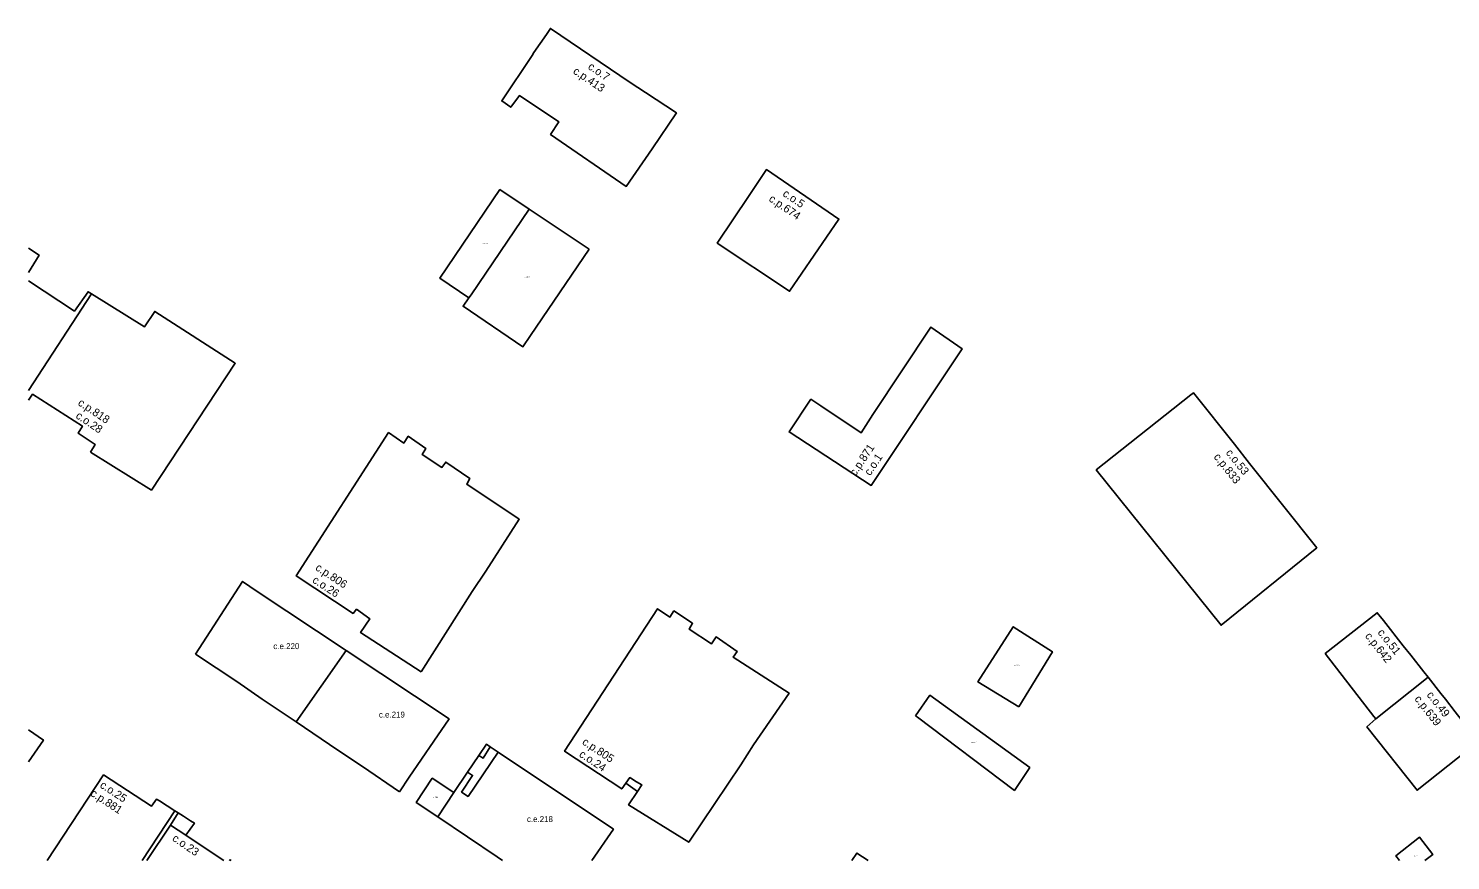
# Model space of a CAD drawing. Extents: x -600391 to -599491, y -1160176 to -1159402.
# Drawn here: x -600391 to -600213.3, y -1160176.1 to -1160072.1 of the extents above; entities that cross this region are included whole.
import ezdxf

# ---------------------------------------------------------------- set-up
doc = ezdxf.new("R2010")
doc.units = 0
for name, color, linetype in [('Level 10', 7, 'Continuous'), ('Level 12', 7, 'Continuous'), ('Level 23', 7, 'Continuous'), ('Level 24', 7, 'Continuous'), ('Level 25', 7, 'Continuous'), ('Level 61', 7, 'Continuous'), ('Level 62', 7, 'Continuous')]:
    doc.layers.add(name, color=color, linetype=linetype)

msp = doc.modelspace()

# ---------------------------------------------------------------- linework, layer by layer
at = {"layer": 'Level 61'}
for p, q in [((-600391.01, -1160099.58), (-600389.68, -1160100.46)), ((-600389.68, -1160100.46), (-600391.01, -1160102.63)), ((-600391.01, -1160103.69), (-600385.27, -1160107.44)), ((-600391.01, -1160117.37), (-600383.14, -1160105.31)), ((-600383.14, -1160105.31), (-600391.01, -1160117.37)), ((-600390.49, -1160117.84), (-600391.01, -1160118.58)), ((-600391.01, -1160159.77), (-600389.13, -1160161.03)), ((-600389.13, -1160161.03), (-600391.01, -1160163.76)), ((-600388.66, -1160176.08), (-600381.61, -1160165.38)), ((-600372.71, -1160169.85), (-600376.79, -1160176.08)), ((-600376.79, -1160176.08), (-600372.71, -1160169.85)), ((-600376.2, -1160176.08), (-600373.25, -1160171.64)), ((-600373.25, -1160171.64), (-600376.2, -1160176.08)), ((-600317.91, -1160172.18), (-600320.58, -1160176.08)), ((-600371.18, -1160173.02), (-600366.61, -1160176.08)), ((-600365.92, -1160176.08), (-600365.83, -1160175.97)), ((-600365.83, -1160175.97), (-600365.67, -1160176.08)), ((-600331.75, -1160176.08), (-600332.43, -1160175.62)), ((-600288.1, -1160176.08), (-600287.48, -1160175.15)), ((-600287.48, -1160175.15), (-600286.05, -1160176.08)), ((-600219.66, -1160176.08), (-600220.12, -1160175.48)), ((-600215.49, -1160175.31), (-600216.48, -1160176.08))]:
    msp.add_line(p, q, dxfattribs=at)
for points in [[(-600327.83, -1160075.17), (-600326.26, -1160072.9)], [(-600326.26, -1160072.9), (-600325.77, -1160072.15)], [(-600325.77, -1160072.15), (-600315.8, -1160078.89)], [(-600331.86, -1160081.2), (-600328.06, -1160075.52)], [(-600328.06, -1160075.52), (-600327.83, -1160075.17)], [(-600315.8, -1160078.89), (-600313.88, -1160080.16)], [(-600330.74, -1160082), (-600331.86, -1160081.2)], [(-600329.65, -1160080.53), (-600330.74, -1160082)], [(-600324.72, -1160083.83), (-600329.65, -1160080.53)], [(-600313.88, -1160080.16), (-600310.04, -1160082.7)], [(-600310.04, -1160082.7), (-600313.05, -1160087.19)], [(-600325.76, -1160085.39), (-600324.72, -1160083.83)], [(-600316.29, -1160091.88), (-600325.76, -1160085.39)], [(-600313.05, -1160087.19), (-600316.29, -1160091.88)], [(-600300.94, -1160093), (-600298.78, -1160089.78)], [(-600298.78, -1160089.78), (-600289.73, -1160095.96)], [(-600339.59, -1160103.35), (-600332.09, -1160092.28)], [(-600332.09, -1160092.28), (-600328.45, -1160094.71)], [(-600304.92, -1160098.95), (-600300.94, -1160093)], [(-600335.7, -1160105.41), (-600328.45, -1160094.71)], [(-600328.45, -1160094.71), (-600335.7, -1160105.41)], [(-600328.45, -1160094.71), (-600320.95, -1160099.71)], [(-600289.73, -1160095.96), (-600295.89, -1160104.97)], [(-600295.89, -1160104.97), (-600304.92, -1160098.95)], [(-600320.95, -1160099.71), (-600328.26, -1160110.5)], [(-600335.97, -1160105.81), (-600339.59, -1160103.35)], [(-600385.27, -1160107.44), (-600383.56, -1160105.03)], [(-600383.56, -1160105.03), (-600383.14, -1160105.31)], [(-600383.14, -1160105.31), (-600376.51, -1160109.43)], [(-600336.68, -1160106.85), (-600335.97, -1160105.81)], [(-600335.97, -1160105.81), (-600335.7, -1160105.41)], [(-600335.7, -1160105.41), (-600335.97, -1160105.81)], [(-600376.51, -1160109.43), (-600375.23, -1160107.5)], [(-600375.23, -1160107.5), (-600365.17, -1160113.96)], [(-600329.21, -1160111.91), (-600336.68, -1160106.85)], [(-600285.49, -1160120.38), (-600278.22, -1160109.45)], [(-600278.22, -1160109.45), (-600274.33, -1160112.15)], [(-600328.26, -1160110.5), (-600329.21, -1160111.91)], [(-600274.33, -1160112.15), (-600285.69, -1160129.22)], [(-600365.17, -1160113.96), (-600375.65, -1160129.81)], [(-600384.27, -1160121.81), (-600390.49, -1160117.84)], [(-600295.94, -1160122.55), (-600293.23, -1160118.46)], [(-600293.23, -1160118.46), (-600291.98, -1160119.29)], [(-600257.57, -1160127.29), (-600245.75, -1160117.93)], [(-600245.75, -1160117.93), (-600245.57, -1160117.78)], [(-600245.57, -1160117.78), (-600245.41, -1160117.66)], [(-600245.41, -1160117.66), (-600240.3, -1160124.09)], [(-600291.98, -1160119.29), (-600286.95, -1160122.66)], [(-600286.95, -1160122.66), (-600285.49, -1160120.38)], [(-600384.8, -1160122.69), (-600384.27, -1160121.81)], [(-600382.65, -1160124.12), (-600384.8, -1160122.69)], [(-600357.55, -1160140.52), (-600346.01, -1160122.62)], [(-600346.01, -1160122.62), (-600344.11, -1160123.93)], [(-600285.69, -1160129.22), (-600295.94, -1160122.55)], [(-600383.27, -1160125.06), (-600382.65, -1160124.12)], [(-600344.11, -1160123.93), (-600343.55, -1160123.08)], [(-600343.55, -1160123.08), (-600341.34, -1160124.63)], [(-600240.3, -1160124.09), (-600238.4, -1160126.47)], [(-600375.65, -1160129.81), (-600383.27, -1160125.06)], [(-600341.34, -1160124.63), (-600341.82, -1160125.36)], [(-600341.82, -1160125.36), (-600339.33, -1160126.98)], [(-600339.33, -1160126.98), (-600338.85, -1160126.31)], [(-600338.85, -1160126.31), (-600335.86, -1160128.36)], [(-600241.96, -1160146.7), (-600257.57, -1160127.29)], [(-600238.4, -1160126.47), (-600230.01, -1160137.02)], [(-600335.86, -1160128.36), (-600336.24, -1160129.07)], [(-600336.24, -1160129.07), (-600329.67, -1160133.45)], [(-600329.67, -1160133.45), (-600333.84, -1160139.93)], [(-600230.01, -1160137.02), (-600241.96, -1160146.7)], [(-600333.84, -1160139.93), (-600335.54, -1160142.49)], [(-600370.15, -1160150.29), (-600364.25, -1160141.21)], [(-600364.25, -1160141.21), (-600362.41, -1160142.46)], [(-600350.43, -1160145.22), (-600357.55, -1160140.52)], [(-600362.41, -1160142.46), (-600351.29, -1160149.85)], [(-600335.54, -1160142.49), (-600341.92, -1160152.51)], [(-600350, -1160144.7), (-600350.43, -1160145.22)], [(-600348.35, -1160145.88), (-600350, -1160144.7)], [(-600324, -1160162.42), (-600312.38, -1160144.63)], [(-600312.38, -1160144.63), (-600310.85, -1160145.67)], [(-600310.85, -1160145.67), (-600310.34, -1160144.89)], [(-600310.34, -1160144.89), (-600308, -1160146.44)], [(-600228.95, -1160150.22), (-600222.45, -1160145.12)], [(-600222.45, -1160145.12), (-600221.68, -1160146.1)], [(-600349.5, -1160147.61), (-600348.35, -1160145.88)], [(-600308, -1160146.44), (-600308.43, -1160147.18)], [(-600308.43, -1160147.18), (-600305.63, -1160149.01)], [(-600272.36, -1160153.77), (-600267.93, -1160146.87)], [(-600267.93, -1160146.87), (-600263.05, -1160150)], [(-600221.68, -1160146.1), (-600219.19, -1160149.25)], [(-600341.92, -1160152.51), (-600349.5, -1160147.61)], [(-600305.63, -1160149.01), (-600305.08, -1160148.14)], [(-600305.08, -1160148.14), (-600302.44, -1160149.95)], [(-600219.19, -1160149.25), (-600218.26, -1160150.42)], [(-600364.98, -1160153.72), (-600370.15, -1160150.29)], [(-600351.29, -1160149.85), (-600357.57, -1160158.77)], [(-600357.57, -1160158.77), (-600351.29, -1160149.85)], [(-600351.29, -1160149.85), (-600338.44, -1160158.39)], [(-600302.44, -1160149.95), (-600302.92, -1160150.68)], [(-600302.92, -1160150.68), (-600295.94, -1160155.17)], [(-600263.05, -1160150), (-600267.22, -1160156.88)], [(-600222.86, -1160158.07), (-600228.95, -1160150.22)], [(-600218.26, -1160150.42), (-600216.61, -1160152.51)], [(-600216.61, -1160152.51), (-600216.09, -1160153.17)], [(-600361.8, -1160155.92), (-600364.98, -1160153.72)], [(-600267.22, -1160156.88), (-600272.36, -1160153.77)], [(-600216.09, -1160153.17), (-600222.61, -1160158.36)], [(-600222.61, -1160158.36), (-600216.09, -1160153.17)], [(-600216.09, -1160153.17), (-600214.49, -1160155.22)], [(-600357.57, -1160158.77), (-600361.8, -1160155.92)], [(-600295.94, -1160155.17), (-600300.38, -1160161.62)], [(-600280.15, -1160158.01), (-600278.35, -1160155.43)], [(-600278.35, -1160155.43), (-600265.87, -1160164.47)], [(-600214.49, -1160155.22), (-600213.93, -1160155.94)], [(-600213.93, -1160155.94), (-600212.69, -1160157.52)], [(-600279.92, -1160158.18), (-600280.15, -1160158.01)], [(-600267.78, -1160167.33), (-600279.92, -1160158.18)], [(-600222.61, -1160158.36), (-600222.86, -1160158.07)], [(-600352.36, -1160162.28), (-600357.57, -1160158.77)], [(-600338.44, -1160158.39), (-600340.35, -1160161.18)], [(-600223.73, -1160159.37), (-600222.61, -1160158.36)], [(-600217.46, -1160167.3), (-600223.73, -1160159.37)], [(-600340.35, -1160161.18), (-600343.42, -1160165.68)], [(-600334.72, -1160162.94), (-600333.78, -1160161.55)], [(-600333.78, -1160161.55), (-600333.31, -1160161.87)], [(-600300.38, -1160161.62), (-600302, -1160164.14)], [(-600209.81, -1160161.21), (-600217.46, -1160167.3)], [(-600349.28, -1160164.34), (-600352.36, -1160162.28)], [(-600336.15, -1160165.04), (-600334.72, -1160162.94)], [(-600336.06, -1160168.07), (-600332.3, -1160162.55)], [(-600332.3, -1160162.55), (-600336.06, -1160168.07)], [(-600334.17, -1160163.29), (-600334.72, -1160162.94)], [(-600334.72, -1160162.94), (-600334.17, -1160163.29)], [(-600333.31, -1160161.87), (-600334.17, -1160163.29)], [(-600334.17, -1160163.29), (-600333.31, -1160161.87)], [(-600333.31, -1160161.87), (-600332.3, -1160162.55)], [(-600332.3, -1160162.55), (-600317.91, -1160172.18)], [(-600316.86, -1160167.13), (-600324, -1160162.42)], [(-600344.65, -1160167.48), (-600349.28, -1160164.34)], [(-600337.86, -1160167.57), (-600336.15, -1160165.04)], [(-600336.15, -1160165.04), (-600335.51, -1160165.44)], [(-600335.51, -1160165.44), (-600336.15, -1160165.04)], [(-600302, -1160164.14), (-600308.49, -1160173.79)], [(-600265.87, -1160164.47), (-600267.78, -1160167.33)], [(-600381.61, -1160165.38), (-600375.65, -1160169.29)], [(-600343.42, -1160165.68), (-600344.65, -1160167.48)], [(-600342.55, -1160168.81), (-600340.55, -1160165.79)], [(-600340.55, -1160165.79), (-600337.86, -1160167.57)], [(-600335.51, -1160165.44), (-600336.88, -1160167.52)], [(-600336.88, -1160167.52), (-600335.51, -1160165.44)], [(-600316.36, -1160166.41), (-600316.86, -1160167.13)], [(-600316.36, -1160166.41), (-600315.87, -1160165.71)], [(-600315.87, -1160165.71), (-600316.36, -1160166.41)], [(-600314.9, -1160167.47), (-600316.36, -1160166.41)], [(-600315.87, -1160165.71), (-600315.72, -1160165.8)], [(-600315.72, -1160165.8), (-600315.87, -1160165.71)], [(-600315.72, -1160165.8), (-600315.01, -1160166.23)], [(-600315.01, -1160166.23), (-600315.72, -1160165.8)], [(-600315.01, -1160166.23), (-600314.35, -1160166.63)], [(-600314.35, -1160166.63), (-600315.01, -1160166.23)], [(-600314.35, -1160166.63), (-600314.9, -1160167.47)], [(-600314.9, -1160167.47), (-600314.35, -1160166.63)], [(-600375.65, -1160169.29), (-600374.99, -1160168.4)], [(-600374.99, -1160168.4), (-600374.65, -1160168.62)], [(-600374.65, -1160168.62), (-600372.71, -1160169.85)], [(-600339.83, -1160170.62), (-600342.55, -1160168.81)], [(-600339.83, -1160170.62), (-600337.86, -1160167.57)], [(-600337.86, -1160167.57), (-600339.83, -1160170.62)], [(-600336.88, -1160167.52), (-600336.06, -1160168.07)], [(-600336.06, -1160168.07), (-600336.88, -1160167.52)], [(-600316, -1160169.13), (-600314.9, -1160167.47)], [(-600373.25, -1160171.64), (-600372.3, -1160170.11)], [(-600372.3, -1160170.11), (-600373.25, -1160171.64)], [(-600372.71, -1160169.85), (-600372.3, -1160170.11)], [(-600372.3, -1160170.11), (-600371.64, -1160170.53)], [(-600371.64, -1160170.53), (-600370.74, -1160171.11)], [(-600332.43, -1160175.62), (-600339.83, -1160170.62)], [(-600308.49, -1160173.79), (-600316, -1160169.13)], [(-600371.35, -1160172.91), (-600373.25, -1160171.64)], [(-600373.25, -1160171.64), (-600371.35, -1160172.91)], [(-600370.27, -1160171.41), (-600371.35, -1160172.91)], [(-600370.74, -1160171.11), (-600370.27, -1160171.41)], [(-600371.35, -1160172.91), (-600371.18, -1160173.02)], [(-600220.12, -1160175.48), (-600217.16, -1160173.17)], [(-600217.16, -1160173.17), (-600215.49, -1160175.31)]]:
    msp.add_lwpolyline(points, dxfattribs=at)
at = {"layer": 'Level 62'}
msp.add_line((-600373.25, -1160171.64), (-600376.2, -1160176.08), dxfattribs=at)
for points in [[(-600327.83, -1160075.17), (-600326.26, -1160072.9), (-600325.77, -1160072.15), (-600315.8, -1160078.89), (-600313.88, -1160080.16), (-600310.04, -1160082.7), (-600313.05, -1160087.19), (-600316.29, -1160091.88), (-600325.76, -1160085.39), (-600324.72, -1160083.83), (-600329.65, -1160080.53), (-600330.74, -1160082), (-600331.86, -1160081.2), (-600328.06, -1160075.52), (-600327.83, -1160075.17)], [(-600300.94, -1160093), (-600298.78, -1160089.78), (-600289.73, -1160095.96), (-600295.89, -1160104.97), (-600304.92, -1160098.95), (-600300.94, -1160093)], [(-600328.45, -1160094.71), (-600335.7, -1160105.41), (-600335.97, -1160105.81), (-600339.59, -1160103.35), (-600332.09, -1160092.28), (-600328.45, -1160094.71)], [(-600320.95, -1160099.71), (-600328.26, -1160110.5), (-600329.21, -1160111.91), (-600336.68, -1160106.85), (-600335.97, -1160105.81), (-600335.7, -1160105.41), (-600328.45, -1160094.71), (-600320.95, -1160099.71)], [(-600391.01, -1160099.58), (-600389.68, -1160100.46), (-600391.01, -1160102.63)], [(-600391.01, -1160103.69), (-600385.27, -1160107.44), (-600383.56, -1160105.03), (-600383.14, -1160105.31), (-600391.01, -1160117.37)], [(-600391.01, -1160117.37), (-600383.14, -1160105.31), (-600376.51, -1160109.43), (-600375.23, -1160107.5), (-600365.17, -1160113.96), (-600375.65, -1160129.81), (-600383.27, -1160125.06)], [(-600285.49, -1160120.38), (-600278.22, -1160109.45), (-600274.33, -1160112.15), (-600285.69, -1160129.22), (-600295.94, -1160122.55), (-600293.23, -1160118.46), (-600291.98, -1160119.29), (-600286.95, -1160122.66), (-600285.49, -1160120.38)], [(-600383.27, -1160125.06), (-600382.65, -1160124.12), (-600384.8, -1160122.69), (-600384.27, -1160121.81), (-600390.49, -1160117.84), (-600391.01, -1160118.58)], [(-600245.75, -1160117.93), (-600245.57, -1160117.78), (-600245.41, -1160117.66), (-600240.3, -1160124.09), (-600238.4, -1160126.47), (-600230.01, -1160137.02), (-600241.96, -1160146.7), (-600257.57, -1160127.29), (-600245.75, -1160117.93)], [(-600341.92, -1160152.51), (-600349.5, -1160147.61), (-600348.35, -1160145.88), (-600350, -1160144.7), (-600350.43, -1160145.22), (-600357.55, -1160140.52), (-600346.01, -1160122.62), (-600344.11, -1160123.93), (-600343.55, -1160123.08), (-600341.34, -1160124.63), (-600341.82, -1160125.36), (-600339.33, -1160126.98), (-600338.85, -1160126.31), (-600335.86, -1160128.36), (-600336.24, -1160129.07), (-600329.67, -1160133.45), (-600333.84, -1160139.93), (-600335.54, -1160142.49), (-600341.92, -1160152.51)], [(-600370.15, -1160150.29), (-600364.25, -1160141.21), (-600362.41, -1160142.46), (-600351.29, -1160149.85), (-600357.57, -1160158.77), (-600361.8, -1160155.92), (-600364.98, -1160153.72), (-600370.15, -1160150.29)], [(-600316.36, -1160166.41), (-600316.86, -1160167.13), (-600324, -1160162.42), (-600312.38, -1160144.63), (-600310.85, -1160145.67), (-600310.34, -1160144.89), (-600308, -1160146.44), (-600308.43, -1160147.18), (-600305.63, -1160149.01), (-600305.08, -1160148.14), (-600302.44, -1160149.95), (-600302.92, -1160150.68), (-600295.94, -1160155.17), (-600300.38, -1160161.62), (-600302, -1160164.14), (-600308.49, -1160173.79), (-600316, -1160169.13), (-600314.9, -1160167.47), (-600314.35, -1160166.63), (-600315.01, -1160166.23), (-600315.72, -1160165.8), (-600315.87, -1160165.71), (-600316.36, -1160166.41)], [(-600216.09, -1160153.17), (-600222.61, -1160158.36), (-600222.86, -1160158.07), (-600228.95, -1160150.22), (-600222.45, -1160145.12), (-600221.68, -1160146.1), (-600219.19, -1160149.25), (-600218.26, -1160150.42), (-600216.61, -1160152.51), (-600216.09, -1160153.17)], [(-600267.22, -1160156.88), (-600272.36, -1160153.77), (-600267.93, -1160146.87), (-600263.05, -1160150), (-600267.22, -1160156.88)], [(-600344.65, -1160167.48), (-600349.28, -1160164.34), (-600352.36, -1160162.28), (-600357.57, -1160158.77), (-600351.29, -1160149.85), (-600338.44, -1160158.39), (-600340.35, -1160161.18), (-600343.42, -1160165.68), (-600344.65, -1160167.48)], [(-600214.49, -1160155.22), (-600213.93, -1160155.94), (-600212.69, -1160157.52), (-600210.6, -1160160.2), (-600209.81, -1160161.21), (-600217.46, -1160167.3), (-600223.73, -1160159.37), (-600222.61, -1160158.36), (-600216.09, -1160153.17), (-600214.49, -1160155.22)], [(-600280.15, -1160158.01), (-600278.35, -1160155.43), (-600265.87, -1160164.47), (-600267.78, -1160167.33), (-600279.92, -1160158.18), (-600280.15, -1160158.01)], [(-600391.01, -1160159.77), (-600389.13, -1160161.03), (-600391.01, -1160163.76)], [(-600333.31, -1160161.87), (-600334.17, -1160163.29), (-600334.72, -1160162.94), (-600333.78, -1160161.55), (-600333.31, -1160161.87)], [(-600331.75, -1160176.08), (-600332.43, -1160175.62), (-600339.83, -1160170.62), (-600337.86, -1160167.57), (-600336.15, -1160165.04), (-600335.51, -1160165.44), (-600336.88, -1160167.52), (-600336.06, -1160168.07), (-600332.3, -1160162.55), (-600317.91, -1160172.18), (-600320.58, -1160176.08)], [(-600333.31, -1160161.87), (-600332.3, -1160162.55), (-600336.06, -1160168.07), (-600336.88, -1160167.52), (-600335.51, -1160165.44), (-600336.15, -1160165.04), (-600334.72, -1160162.94), (-600334.17, -1160163.29), (-600333.31, -1160161.87)], [(-600388.66, -1160176.08), (-600381.61, -1160165.38), (-600375.65, -1160169.29), (-600374.99, -1160168.4), (-600374.65, -1160168.62), (-600372.71, -1160169.85), (-600376.79, -1160176.08)], [(-600339.83, -1160170.62), (-600342.55, -1160168.81), (-600340.55, -1160165.79), (-600337.86, -1160167.57), (-600339.83, -1160170.62)], [(-600316.36, -1160166.41), (-600315.87, -1160165.71), (-600315.72, -1160165.8), (-600315.01, -1160166.23), (-600314.35, -1160166.63), (-600314.9, -1160167.47), (-600316.36, -1160166.41)], [(-600376.79, -1160176.08), (-600372.71, -1160169.85), (-600372.3, -1160170.11), (-600373.25, -1160171.64)], [(-600373.25, -1160171.64), (-600372.3, -1160170.11), (-600371.64, -1160170.53), (-600370.74, -1160171.11), (-600370.27, -1160171.41), (-600371.35, -1160172.91), (-600373.25, -1160171.64)], [(-600376.2, -1160176.08), (-600373.25, -1160171.64), (-600371.35, -1160172.91), (-600371.18, -1160173.02), (-600366.61, -1160176.08)], [(-600219.66, -1160176.08), (-600220.12, -1160175.48), (-600217.16, -1160173.17), (-600215.49, -1160175.31), (-600216.48, -1160176.08)], [(-600365.92, -1160176.08), (-600365.83, -1160175.97), (-600365.67, -1160176.08)], [(-600288.1, -1160176.08), (-600287.48, -1160175.15), (-600286.05, -1160176.08)]]:
    msp.add_lwpolyline(points, dxfattribs=at)

# ---------------------------------------------------------------- texts
at = {"layer": 'Level 10'}
for s, rotation, p in [('c.o.7', 325.9397, (-600321.18, -1160077.13)), ('c.o.5', 325.6727, (-600296.84, -1160092.99)), ('c.o.28', 326.1463, (-600385.19, -1160120.74)), ('c.o.1', 56.3576, (-600285.82, -1160128.09)), ('c.o.53', 308.4916, (-600241.43, -1160125.17)), ('c.o.26', 326.5721, (-600355.62, -1160141.27)), ('c.o.51', 308.3082, (-600222.46, -1160147.62)), ('c.o.49', 307.9941, (-600216.32, -1160155.41)), ('c.o.24', 326.5896, (-600322.28, -1160163.03)), ('c.o.25', 326.7342, (-600382.17, -1160166.88)), ('c.o.23', 325.7013, (-600373.13, -1160173.52))]:
    msp.add_text(s, height=1, rotation=rotation, dxfattribs=at).set_placement(p)
at = {"layer": 'Level 12'}
for s, rotation, p in [('c.p.413', 325.9397, (-600323.04, -1160077.7)), ('c.p.674', 325.6727, (-600298.57, -1160093.64)), ('c.p.818', 326.1463, (-600384.92, -1160119.12)), ('c.p.871', 56.3576, (-600287.65, -1160128.13)), ('c.p.833', 308.4916, (-600242.94, -1160125.69)), ('c.p.806', 326.5721, (-600355.24, -1160139.72)), ('c.p.642', 308.3082, (-600224.03, -1160148.06)), ('c.p.639', 307.9941, (-600217.85, -1160155.92)), ('c.p.805', 326.5896, (-600321.9, -1160161.49)), ('c.p.881', 326.7342, (-600383.35, -1160167.91))]:
    msp.add_text(s, height=1, rotation=rotation, dxfattribs=at).set_placement(p)
at = {"layer": 'Level 23'}
for s, p in [('c.e.220', (-600360.4, -1160149.67)), ('c.e.219', (-600347.21, -1160158.22)), ('c.e.218', (-600328.71, -1160171.27))]:
    msp.add_text(s, height=0.74, dxfattribs=at).set_placement(p)
at = {"layer": 'Level 24'}
msp.add_text('c.z.270', height=0.1, dxfattribs=at).set_placement((-600217.85, -1160175.55))
at = {"layer": 'Level 25'}
for s, p in [('c.pp.413_A', (-600334.32, -1160099.04)), ('c.pp.413_B', (-600329.04, -1160103.22)), ('c.pp.833_A', (-600267.83, -1160151.73)), ('c.pp.835_A', (-600273.23, -1160161.34)), ('c.pp.805_B', (-600340.52, -1160168.22))]:
    msp.add_text(s, height=0.1, dxfattribs=at).set_placement(p)

doc.saveas('drawing.dxf')
